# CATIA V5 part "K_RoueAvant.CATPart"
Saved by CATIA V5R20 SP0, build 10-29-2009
Part number: roue_avant_volume
Bounding box of the stored display mesh (mm): x 750.021 to 949.979, y -34.995 to 34.995, z -199.979 to -0.021
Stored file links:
  G:\Khaled_CFAO_2011\ST2M\ST2M_GR1\cdurantin\cdurantin\Khaled\CAD_ThinkMOTION\K_RoueAvant.CATPart
  C:\Documents and Settings\cdurantin\Bureau\cdurantin\caddy.CATProduct
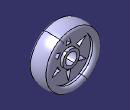
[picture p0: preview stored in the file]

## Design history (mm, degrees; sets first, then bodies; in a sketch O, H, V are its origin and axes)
Parameters
  `diamètre ext roue avant` = 200 mm
  `épaisseur pneu` = 20 mm
External parameters (linked from other documents)
  `External.diamètre des barres` = 40 mm
  `External.Surepaisseur du tube` = 10 mm
  `External.niveau de la roue avant` = 850 mm
  `External.hauteur roue avant` = 100 mm
  `External.diamètre moyeux` = 100 mm
Set1
  Point1: linked copy from another document
  Line1: linked copy from another document
  Line2: linked copy from another document
Body1 (main body)
  Plane1: type Offset, RefPlane yz-plane, Offset 850 {= `External.niveau de la roue avant`}
  Sketch1 on Plane1, origin (850, 0, 0), H (0, 1, 0), V (0, 0, 1)
    line L1 (-22.5, -70) -> (-22.5, -80)
    line L2 (-22.5, -80) -> (22.5, -80)
    line L3 (22.5, -80) -> (22.5, -70)
    line L4 (22.5, -70) -> (12.5, -70)
    line L5 (12.5, -70) -> (12.5, -20.9826)
    line L6 (-12.5, -20.9826) -> (-12.5, -70)
    point P6 (-12.5, -70)
    line L7 (-12.5, -70) -> (-22.5, -70)
    arc A1 centre (0, -100) radius 100 from (27.7778, -3.9355) to (-27.7778, -3.9355) ccw
    reference projected point E2 (0, -100) from Point1
    arc A2 centre (-25, -13.5419) radius 10 from (-27.7778, -3.9355) to (-22.2222, -23.1484) ccw
    point P8 (-25, -13.5419)
    arc A3 centre (25, -13.5419) radius 10 from (22.2222, -23.1484) to (27.7778, -3.9355) ccw
    point P9 (25, -13.5419)
    reference projected line E4 (0, -100) -> (0, -50) from Line1
    arc A4 centre (0, -100) radius 80 from (22.2222, -23.1484) to (12.5, -20.9826) ccw
    reference projected line E5 (0, -100) -> (0, -50) from Line1
    reference projected line E6 (0, -100) -> (0, -50) from Line1
    reference projected line E7 (-50, -100) -> (0, -100) from Line2
    point P16 (-12.5, -20.9826)
    arc A5 centre (0, -100) radius 80 from (-12.5, -20.9826) to (-22.2222, -23.1484) ccw
    radius A1 = 100 {= `diamètre ext roue avant` /2}
    radius A3 = 10 {= `épaisseur pneu` /2}
    radius A2 = 10 {= `épaisseur pneu` /2}
    distance P9 P8 = 50 {= (`External.diamètre moyeux` )/2}
    distance P8 E4 = 25 {= `External.diamètre moyeux` /4}
    distance L6 L5 = 25 {= `External.diamètre moyeux` /4}
    distance E5 L5 = 12.5 {= `External.diamètre moyeux` /8}
    length L2 = 45 {= (`External.diamètre moyeux` -`External.diamètre moyeux` /10)/2}
    distance E6 L3 = 22.5 {= (`External.diamètre moyeux` /2-`External.diamètre moyeux` /20)/2}
    distance L2 E7 = 20 {= `External.diamètre des barres` /2}
    length L3 = 10 {= `External.Surepaisseur du tube`}
    vertical: L1 V, L3 V, L5 V, L6 V
    horizontal: L2 H, L4 H, L7 H
    coincidence: P6 L4, A4 P16, A4 A5
    concentricity: E2 A1
    tangency: A2 A1, A3 A1, A4 A3
  Shaft1: profile Sketch1, axis Line2, angle 360
  Sketch2 on face of Shaft1 from Sketch1.L5, origin (0, 12.5, 0), H (-1, 0, 0), V (0, 0, 1)
    arc A1 centre (-850, -100) radius 40 from (-840.7797, -61.0772) to (-859.2203, -61.0772) ccw
    point P1 (-850, -26.6667)
    line L1 (-850, -26.6667) -> (-859.2203, -61.0772)
    line L2 (-850, -26.6667) -> (-840.7797, -61.0772)
    reference projected line E2 (-850, -100) -> (-850, -50) from Line1
    reference projected line E3 (-850, -100) -> (-850, -50) from Line1
    radius A1 = 40 {= `External.diamètre des barres` /2+2*`External.Surepaisseur du tube`}
    distance P1 A1 = 33.3333 {= `diamètre ext roue avant` /6}
    angle L1 L2 = 30
    angle L2 E2 = 15
    distance P1 E3 = 0
  Pocket1: profile Sketch2, direction (0, -1, 0), up to face of Shaft1 from Sketch1.L6
  CircPattern1: of Pocket1, instances 6, angular step 60, axis from face of Shaft1 from Sketch1.L4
